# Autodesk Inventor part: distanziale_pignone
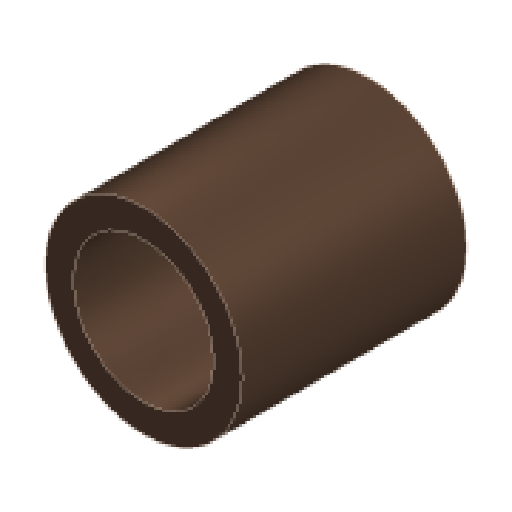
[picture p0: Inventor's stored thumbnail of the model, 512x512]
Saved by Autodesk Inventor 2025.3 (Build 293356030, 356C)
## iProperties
Created: 2026-05
Part Number: distanziale_pignone
Material: Bronzo, Stagno dolce
Document SubType Name: Modeling
Designer: R5800u
Density: 8.874 g/cm^3
Appearance: Bronzo - Satinato
Author: R5800u
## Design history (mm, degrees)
sketch "Schizzo1"
  geometry: C1 r 12.5 at (0, 0); C2 r 17.5 at (0, 0); 1 further point
  constraints: 2 centre point, 1 coincident
  dimensions: "d0" = 25 diameter of C1; "d1" = 5 radial gap between concentric circles of C1 C2
extrude "Estrusione1" new body sketch "Schizzo1" distance "d2" = 40; taper "d3" = 0 deg
node "Solido1"
